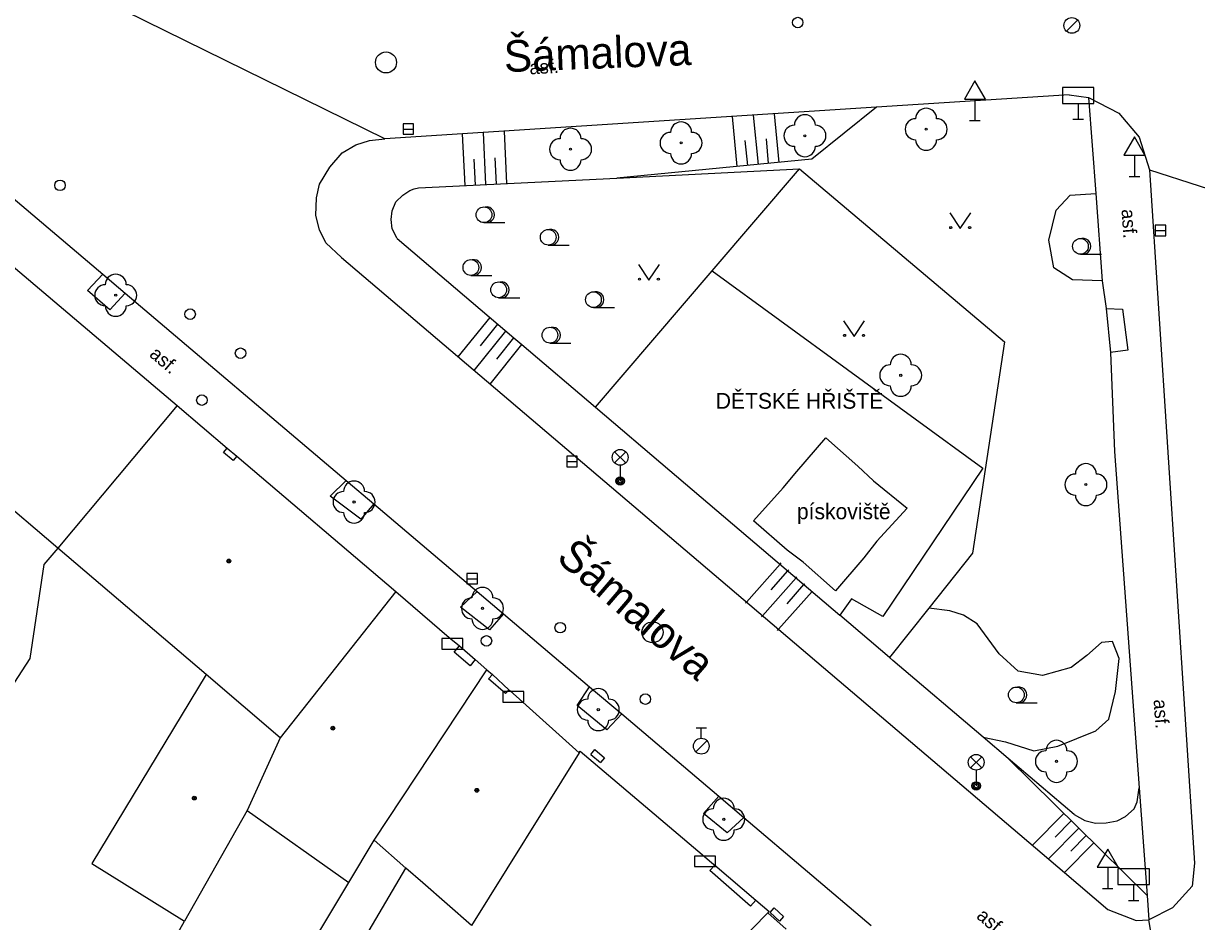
# Model space of a CAD drawing. Extents: x -596229 to -595156, y -1161237 to -1159376.
# Drawn here: x -596136.3 to -596080.4, y -1161085 to -1161042.3 of the extents above; entities that cross this region are included whole.
import ezdxf

# ---------------------------------------------------------------- set-up
doc = ezdxf.new("R2010")
doc.units = 0
for name, color, linetype in [('DOP - rozhrani ploch obecne', 7, 'Continuous'), ('Level 22', 7, 'Continuous'), ('Level 24', 7, 'Continuous'), ('Level 27', 7, 'Continuous'), ('Level 28', 7, 'Continuous'), ('Level 33', 7, 'Continuous'), ('Level 34', 7, 'Continuous'), ('Level 36', 7, 'Continuous'), ('Level 39', 7, 'Continuous'), ('Nazvy ulic', 7, 'Continuous'), ('silnoproud - povrch.  znaky a  RIS  skut. velikost', 7, 'Continuous'), ('slaboproud - povrch.  znaky a tel. budka skut. velikost', 7, 'Continuous'), ('Specificka linie pasportu komunikaci', 7, 'Continuous'), ('TM - budovy zdene_ betonove - NP', 7, 'Continuous'), ('TM - budovy zdene_ betonove - VP', 7, 'Continuous'), ('TM - chodniky - VP', 7, 'Continuous'), ('TM - horni hrana svahu', 7, 'Continuous'), ('TM - komunikace - VP', 7, 'Continuous'), ('TM - letecke snimky - pomocna linie', 7, 'Continuous'), ('TM - popis objektu', 7, 'Continuous'), ('TM - popis povrchu', 7, 'Continuous'), ('TM - poznamka', 7, 'Continuous'), ('TM - rozhrani kultur', 7, 'Continuous'), ('TM - rozhrani ploch obecne - VP', 7, 'Continuous'), ('TM - srafovani', 7, 'Continuous')]:
    doc.layers.add(name, color=color, linetype=linetype)

msp = doc.modelspace()

# ---------------------------------------------------------------- linework, layer by layer
at = {"layer": 'DOP - rozhrani ploch obecne'}
for points in [[(-596134.63, -1161067.25), (-596135.29, -1161068.02)], [(-596135.29, -1161068.02), (-596135.95, -1161072.49)], [(-596135.95, -1161072.49), (-596144.77, -1161086.08)], [(-596120.78, -1161083.15), (-596119.57, -1161081.14)], [(-596124.19, -1161088.83), (-596120.78, -1161083.15)], [(-596129.54, -1161086.67), (-596128.6, -1161085)]]:
    msp.add_lwpolyline(points, dxfattribs=at)
at = {"layer": 'Level 22'}
for centre in [(-596093.31, -1161047.31), (-596104.97, -1161047.96), (-596099.08, -1161047.62), (-596110.23, -1161048.26), (-596131.87, -1161055.21), (-596094.52, -1161059.02), (-596085.71, -1161064.22), (-596120.53, -1161065.05), (-596114.42, -1161070.11), (-596108.91, -1161074.93), (-596087.11, -1161077.39), (-596102.94, -1161080.15)]:
    msp.add_circle(centre, 0.05, dxfattribs=at)
for centre, start, end in [((-596093.31, -1161046.81), 0, 180), ((-596099.08, -1161047.12), 0, 180), ((-596093.81, -1161047.31), 90, 270), ((-596092.81, -1161047.31), 270, 90), ((-596110.23, -1161047.76), 0, 180), ((-596104.97, -1161047.46), 0, 180), ((-596099.58, -1161047.62), 90, 270), ((-596098.58, -1161047.62), 270, 90), ((-596110.73, -1161048.26), 90, 270), ((-596109.73, -1161048.26), 270, 90), ((-596105.47, -1161047.96), 90, 270), ((-596104.47, -1161047.96), 270, 90), ((-596093.31, -1161047.81), 180, 0), ((-596104.97, -1161048.46), 180, 0), ((-596099.08, -1161048.12), 180, 0), ((-596110.23, -1161048.76), 180, 0), ((-596131.87, -1161054.71), 0, 180), ((-596132.37, -1161055.21), 90, 270), ((-596131.37, -1161055.21), 270, 90), ((-596131.87, -1161055.71), 180, 0), ((-596094.52, -1161058.52), 0, 180), ((-596095.02, -1161059.02), 90, 270), ((-596094.02, -1161059.02), 270, 90), ((-596094.52, -1161059.52), 180, 0), ((-596085.71, -1161063.72), 0, 180), ((-596120.53, -1161064.55), 0, 180), ((-596086.21, -1161064.22), 90, 270), ((-596085.21, -1161064.22), 270, 90), ((-596121.03, -1161065.05), 90, 270), ((-596120.03, -1161065.05), 270, 90), ((-596085.71, -1161064.72), 180, 0), ((-596120.53, -1161065.55), 180, 0), ((-596114.42, -1161069.61), 0, 180), ((-596114.92, -1161070.11), 90, 270), ((-596113.92, -1161070.11), 270, 90), ((-596114.42, -1161070.61), 180, 0), ((-596108.91, -1161074.43), 0, 180), ((-596109.41, -1161074.93), 90, 270), ((-596108.41, -1161074.93), 270, 90), ((-596108.91, -1161075.43), 180, 0), ((-596087.11, -1161076.89), 0, 180), ((-596087.61, -1161077.39), 90, 270), ((-596086.61, -1161077.39), 270, 90), ((-596087.11, -1161077.89), 180, 0), ((-596102.94, -1161079.65), 0, 180), ((-596103.44, -1161080.15), 90, 270), ((-596102.44, -1161080.15), 270, 90), ((-596102.94, -1161080.65), 180, 0)]:
    msp.add_arc(centre, 0.5, start, end, dxfattribs=at)
at = {"layer": 'Level 24'}
for points in [[(-596116.347, -1161072.048), (-596115.347, -1161072.048), (-596115.347, -1161071.548), (-596116.347, -1161071.548)], [(-596113.447, -1161074.568), (-596112.447, -1161074.568), (-596112.447, -1161074.068), (-596113.447, -1161074.068)], [(-596104.337, -1161082.398), (-596103.337, -1161082.398), (-596103.337, -1161081.898), (-596104.337, -1161081.898)]]:
    msp.add_lwpolyline(points, close=True, dxfattribs=at)
at = {"layer": 'Level 27'}
for p, q in [((-596118.2, -1161047.3), (-596117.7, -1161047.3)), ((-596082.41, -1161052.13), (-596081.91, -1161052.13)), ((-596110.41, -1161063.12), (-596109.91, -1161063.12)), ((-596115.16, -1161068.7), (-596114.66, -1161068.7))]:
    msp.add_line(p, q, dxfattribs=at)
for points in [[(-596118.2, -1161047.55), (-596117.7, -1161047.55), (-596117.7, -1161047.05), (-596118.2, -1161047.05)], [(-596082.41, -1161052.38), (-596081.91, -1161052.38), (-596081.91, -1161051.88), (-596082.41, -1161051.88)], [(-596110.41, -1161063.37), (-596109.91, -1161063.37), (-596109.91, -1161062.87), (-596110.41, -1161062.87)], [(-596115.16, -1161068.95), (-596114.66, -1161068.95), (-596114.66, -1161068.45), (-596115.16, -1161068.45)]]:
    msp.add_lwpolyline(points, close=True, dxfattribs=at)
for centre in [(-596119.01, -1161044.13), (-596106.33, -1161071.25)]:
    msp.add_circle(centre, 0.5, dxfattribs=at)
at = {"layer": 'Level 28'}
for p, q in [((-596086.638, -1161042.642), (-596086.108, -1161042.112)), ((-596104.26, -1161075.795), (-596103.76, -1161075.795)), ((-596104.01, -1161076.295), (-596104.01, -1161075.795)), ((-596104.268, -1161076.942), (-596103.738, -1161076.412))]:
    msp.add_line(p, q, dxfattribs=at)
for centre, radius in [((-596099.42, -1161042.23), 0.25), ((-596086.38, -1161042.37), 0.375), ((-596134.52, -1161049.98), 0.25), ((-596128.33, -1161056.11), 0.25), ((-596125.93, -1161057.97), 0.25), ((-596127.77, -1161060.2), 0.25), ((-596110.72, -1161071.03), 0.25), ((-596114.23, -1161071.66), 0.25), ((-596106.67, -1161074.43), 0.25), ((-596104.01, -1161076.67), 0.375)]:
    msp.add_circle(centre, radius, dxfattribs=at)
at = {"layer": 'Level 33'}
for p, q in [((-596108.135, -1161063.19), (-596107.605, -1161062.66)), ((-596108.135, -1161062.66), (-596107.605, -1161063.19)), ((-596107.87, -1161063.3), (-596107.87, -1161064.05)), ((-596091.195, -1161077.7), (-596090.665, -1161077.17)), ((-596091.195, -1161077.17), (-596090.665, -1161077.7)), ((-596090.93, -1161077.81), (-596090.93, -1161078.56))]:
    msp.add_line(p, q, dxfattribs=at)
for centre, radius in [((-596107.87, -1161062.925), 0.375), ((-596107.87, -1161064.05), 0.2), ((-596107.87, -1161064.05), 0.145), ((-596107.87, -1161064.05), 0.0876), ((-596090.93, -1161077.435), 0.375), ((-596090.93, -1161078.56), 0.2), ((-596090.93, -1161078.56), 0.145), ((-596090.93, -1161078.56), 0.0876)]:
    msp.add_circle(centre, radius, dxfattribs=at)
at = {"layer": 'Level 34'}
for p, q in [((-596090.99, -1161045.872), (-596090.99, -1161046.89)), ((-596086.08, -1161046.08), (-596086.08, -1161046.83)), ((-596086.33, -1161046.83), (-596085.83, -1161046.83)), ((-596091.24, -1161046.89), (-596090.74, -1161046.89)), ((-596083.4, -1161048.542), (-596083.4, -1161049.56)), ((-596083.65, -1161049.56), (-596083.15, -1161049.56)), ((-596084.67, -1161082.432), (-596084.67, -1161083.45)), ((-596084.92, -1161083.45), (-596084.42, -1161083.45)), ((-596083.44, -1161083.26), (-596083.44, -1161084.01)), ((-596083.69, -1161084.01), (-596083.19, -1161084.01))]:
    msp.add_line(p, q, dxfattribs=at)
for points in [[(-596091.49, -1161045.872), (-596090.49, -1161045.872), (-596090.99, -1161045.006)], [(-596086.83, -1161046.08), (-596085.33, -1161046.08), (-596085.33, -1161045.33), (-596086.83, -1161045.33)], [(-596083.9, -1161048.542), (-596082.9, -1161048.542), (-596083.4, -1161047.676)], [(-596085.17, -1161082.432), (-596084.17, -1161082.432), (-596084.67, -1161081.566)], [(-596084.19, -1161083.26), (-596082.69, -1161083.26), (-596082.69, -1161082.51), (-596084.19, -1161082.51)]]:
    msp.add_lwpolyline(points, close=True, dxfattribs=at)
at = {"layer": 'Level 36'}
for p, q in [((-596114.35, -1161051.755), (-596113.35, -1161051.755)), ((-596111.29, -1161052.825), (-596110.29, -1161052.825)), ((-596085.97, -1161053.255), (-596084.97, -1161053.255)), ((-596114.97, -1161054.265), (-596113.97, -1161054.265)), ((-596113.65, -1161055.325), (-596112.65, -1161055.325)), ((-596109.14, -1161055.795), (-596108.14, -1161055.795)), ((-596111.21, -1161057.485), (-596110.21, -1161057.485)), ((-596089.02, -1161074.605), (-596088.02, -1161074.605))]:
    msp.add_line(p, q, dxfattribs=at)
for points in [[(-596092.19, -1161051.29), (-596091.69, -1161052.04), (-596091.19, -1161051.29)], [(-596107, -1161053.74), (-596106.5, -1161054.49), (-596106, -1161053.74)], [(-596097.24, -1161056.42), (-596096.74, -1161057.17), (-596096.24, -1161056.42)]]:
    msp.add_lwpolyline(points, dxfattribs=at)
for centre, radius in [((-596114.35, -1161051.38), 0.375), ((-596111.29, -1161052.45), 0.375), ((-596092.14, -1161051.99), 0.05), ((-596091.241, -1161051.99), 0.05), ((-596085.97, -1161052.88), 0.375), ((-596114.97, -1161053.89), 0.375), ((-596113.65, -1161054.95), 0.375), ((-596106.95, -1161054.44), 0.05), ((-596106.051, -1161054.44), 0.05), ((-596109.14, -1161055.42), 0.375), ((-596111.21, -1161057.11), 0.375), ((-596097.19, -1161057.12), 0.05), ((-596096.291, -1161057.12), 0.05), ((-596089.02, -1161074.23), 0.375)]:
    msp.add_circle(centre, radius, dxfattribs=at)
for centre in [(-596114.225, -1161051.38), (-596111.165, -1161052.45), (-596085.845, -1161052.88), (-596114.845, -1161053.89), (-596113.525, -1161054.95), (-596109.015, -1161055.42), (-596111.085, -1161057.11), (-596088.895, -1161074.23)]:
    msp.add_arc(centre, 0.375, 260.4059, 99.5941, dxfattribs=at)
at = {"layer": 'Level 39'}
for centre, radius in [((-596126.49, -1161067.86), 0.09), ((-596126.49, -1161067.86), 0.0398), ((-596121.54, -1161075.81), 0.09), ((-596121.54, -1161075.81), 0.0398), ((-596114.69, -1161078.77), 0.09), ((-596128.13, -1161079.14), 0.09), ((-596128.13, -1161079.14), 0.0398), ((-596114.69, -1161078.77), 0.0398)]:
    msp.add_circle(centre, radius, dxfattribs=at)
at = {"layer": 'silnoproud - povrch.  znaky a  RIS  skut. velikost'}
msp.add_lwpolyline([(-596126.11, -1161062.87), (-596126.29, -1161063.08), (-596126.74, -1161062.69), (-596126.56, -1161062.48)], dxfattribs=at)
at = {"layer": 'slaboproud - povrch.  znaky a tel. budka skut. velikost'}
for points in [[(-596109.27, -1161077.06), (-596109.07, -1161076.83), (-596108.62, -1161077.22), (-596108.81, -1161077.45)], [(-596109.27, -1161077.06), (-596108.81, -1161077.45)], [(-596100.73, -1161084.59), (-596100.54, -1161084.37), (-596100.09, -1161084.77), (-596100.29, -1161084.99)], [(-596100.73, -1161084.59), (-596100.29, -1161084.99)]]:
    msp.add_lwpolyline(points, dxfattribs=at)
at = {"layer": 'Specificka linie pasportu komunikaci'}
for points in [[(-596119.06, -1161047.77), (-596131.42, -1161041.69)], [(-596082.68, -1161049.24), (-596075.59, -1161051.53)], [(-596084.75, -1161055.84), (-596084.54, -1161057.94)], [(-596080.48, -1161098.3), (-596082.72, -1161084.93)]]:
    msp.add_lwpolyline(points, dxfattribs=at)
at = {"layer": 'TM - budovy zdene_ betonove - NP'}
for points in [[(-596114.76, -1161072.55), (-596115.01, -1161072.84), (-596115.76, -1161072.2), (-596115.51, -1161071.9)], [(-596113.16, -1161073.98), (-596113.33, -1161074.17), (-596114.13, -1161073.47), (-596113.95, -1161073.26)], [(-596101.42, -1161083.99), (-596101.66, -1161084.28), (-596103.61, -1161082.59), (-596103.37, -1161082.33)]]:
    msp.add_lwpolyline(points, dxfattribs=at)
at = {"layer": 'TM - budovy zdene_ betonove - VP'}
for points in [[(-596139.98, -1161051.12), (-596128.94, -1161060.45)], [(-596128.94, -1161060.45), (-596134.63, -1161067.25)], [(-596128.94, -1161060.45), (-596126.56, -1161062.48)], [(-596134.63, -1161067.25), (-596140.89, -1161061.91)], [(-596126.56, -1161062.48), (-596126.11, -1161062.87)], [(-596126.11, -1161062.87), (-596118.54, -1161069.31)], [(-596127.57, -1161073.26), (-596134.63, -1161067.25)], [(-596118.54, -1161069.31), (-596124.04, -1161076.27)], [(-596118.54, -1161069.31), (-596116, -1161071.49), (-596115.51, -1161071.9)], [(-596115.51, -1161071.9), (-596114.76, -1161072.55)], [(-596114.76, -1161072.55), (-596114.21, -1161073.03)], [(-596119.57, -1161081.14), (-596114.21, -1161073.03)], [(-596114.21, -1161073.03), (-596113.95, -1161073.26)], [(-596127.57, -1161073.26), (-596133.01, -1161082.25)], [(-596124.04, -1161076.27), (-596127.57, -1161073.26)], [(-596113.95, -1161073.26), (-596113.16, -1161073.98)], [(-596113.16, -1161073.98), (-596113.1, -1161074.03), (-596112.66, -1161074.43), (-596109.82, -1161076.99)], [(-596124.04, -1161076.27), (-596124.44, -1161077.14), (-596125.61, -1161079.73)], [(-596109.82, -1161076.99), (-596114.94, -1161085.2)], [(-596109.82, -1161076.99), (-596109.77, -1161076.9)], [(-596109.77, -1161076.9), (-596103.97, -1161081.82), (-596103.5, -1161082.22), (-596103.37, -1161082.33)], [(-596125.61, -1161079.73), (-596128.6, -1161085)], [(-596118.06, -1161082.47), (-596119.57, -1161081.14)], [(-596133.01, -1161082.25), (-596128.6, -1161085)], [(-596114.94, -1161085.2), (-596117.26, -1161083.17), (-596118.06, -1161082.47)], [(-596103.37, -1161082.33), (-596101.42, -1161083.99)], [(-596101.42, -1161083.99), (-596100.78, -1161084.53)], [(-596102.28, -1161086.07), (-596100.85, -1161084.6)], [(-596100.78, -1161084.53), (-596100.85, -1161084.6)], [(-596100.85, -1161084.6), (-596099.97, -1161085.38)]]:
    msp.add_lwpolyline(points, dxfattribs=at)
at = {"layer": 'TM - chodniky - VP'}
for points in [[(-596085.58, -1161045.8), (-596085.24, -1161050.37)], [(-596085.24, -1161050.37), (-596084.93, -1161054.53)], [(-596131.42, -1161055.11), (-596132.15, -1161055.91), (-596133.22, -1161054.99), (-596132.49, -1161054.2)], [(-596084.93, -1161054.53), (-596084.75, -1161055.84)], [(-596084.75, -1161055.84), (-596083.97, -1161055.87), (-596083.71, -1161057.82), (-596084.54, -1161057.94)], [(-596084.54, -1161057.94), (-596084.35, -1161062.65)], [(-596084.35, -1161062.65), (-596083.18, -1161078.65)], [(-596119.59, -1161065.14), (-596120.21, -1161065.86), (-596121.66, -1161064.77), (-596120.9, -1161064.03)], [(-596113.42, -1161070.37), (-596114.09, -1161071.13), (-596115.46, -1161070.05), (-596114.67, -1161069.31)], [(-596107.79, -1161075.13), (-596108.51, -1161075.89), (-596109.91, -1161074.73), (-596109.32, -1161073.84)], [(-596083.18, -1161078.65), (-596082.8, -1161083.78)], [(-596101.98, -1161080.06), (-596102.78, -1161080.8), (-596103.9, -1161079.87), (-596103.17, -1161079.05)], [(-596082.8, -1161083.78), (-596082.72, -1161084.93)]]:
    msp.add_lwpolyline(points, dxfattribs=at)
at = {"layer": 'TM - horni hrana svahu'}
for points in [[(-596095.67, -1161046.26), (-596098.75, -1161048.74)], [(-596098.75, -1161048.74), (-596108.02, -1161049.63)], [(-596089.41, -1161077.25), (-596082.8, -1161083.78)]]:
    msp.add_lwpolyline(points, dxfattribs=at)
at = {"layer": 'TM - komunikace - VP'}
for points in [[(-596086.5, -1161045.67), (-596095.67, -1161046.26)], [(-596086.5, -1161045.67), (-596085.58, -1161045.8)], [(-596095.67, -1161046.26), (-596119.06, -1161047.77)], [(-596085.58, -1161045.8), (-596084.14, -1161046.54)], [(-596084.14, -1161046.54), (-596083.18, -1161047.69)], [(-596121.13, -1161053.42), (-596121.87, -1161052.72), (-596122.18, -1161052.1), (-596122.35, -1161051.41), (-596122.31, -1161050.58), (-596122.18, -1161049.92), (-596121.69, -1161049.12), (-596121.1, -1161048.43), (-596120.45, -1161048.05), (-596119.79, -1161047.84), (-596119.06, -1161047.77)], [(-596083.18, -1161047.69), (-596082.68, -1161049.24)], [(-596082.68, -1161049.24), (-596080.54, -1161082.23)], [(-596137.07, -1161050.32), (-596132.49, -1161054.2)], [(-596121.13, -1161053.42), (-596086.73, -1161082.68), (-596084.67, -1161084.44), (-596083.31, -1161084.97), (-596082.72, -1161084.93)], [(-596132.49, -1161054.2), (-596131.42, -1161055.11)], [(-596131.42, -1161055.11), (-596120.9, -1161064.03)], [(-596120.9, -1161064.03), (-596119.59, -1161065.14)], [(-596119.59, -1161065.14), (-596114.67, -1161069.31)], [(-596114.67, -1161069.31), (-596113.42, -1161070.37)], [(-596113.42, -1161070.37), (-596109.32, -1161073.84)], [(-596109.32, -1161073.84), (-596107.79, -1161075.13)], [(-596107.79, -1161075.13), (-596103.17, -1161079.05)], [(-596103.17, -1161079.05), (-596101.98, -1161080.06)], [(-596101.98, -1161080.06), (-596095.92, -1161085.2)], [(-596080.54, -1161082.23), (-596080.65, -1161083.33)], [(-596080.65, -1161083.33), (-596081.59, -1161084.37)], [(-596081.59, -1161084.37), (-596082.72, -1161084.93)]]:
    msp.add_lwpolyline(points, dxfattribs=at)
at = {"layer": 'TM - letecke snimky - pomocna linie'}
for points in [[(-596103.49, -1161054.05), (-596099.33, -1161049.2)], [(-596099.33, -1161049.2), (-596089.58, -1161057.43), (-596091.11, -1161067.49), (-596093.19, -1161070.1)], [(-596109.05, -1161060.54), (-596103.49, -1161054.05)], [(-596105.51, -1161063.55), (-596097.41, -1161070.44)], [(-596093.19, -1161070.1), (-596095.05, -1161072.45)], [(-596125.61, -1161079.73), (-596120.78, -1161083.15)], [(-596122.4, -1161089.83), (-596118.06, -1161082.47)]]:
    msp.add_lwpolyline(points, dxfattribs=at)
at = {"layer": 'TM - rozhrani kultur'}
for points in [[(-596084.93, -1161054.53), (-596086.34, -1161054.47), (-596087.24, -1161053.91), (-596087.48, -1161052.59), (-596087.13, -1161051.16), (-596086.46, -1161050.44), (-596085.24, -1161050.37)], [(-596090.6, -1161076.24), (-596089.53, -1161076.46), (-596088.19, -1161076.89), (-596087.05, -1161076.67), (-596085.23, -1161075.94), (-596084.62, -1161075.39), (-596084.3, -1161074.07), (-596084.13, -1161072.5), (-596084.44, -1161071.69), (-596084.97, -1161071.73), (-596085.66, -1161072.35), (-596086.41, -1161072.92), (-596087.77, -1161073.3), (-596088.93, -1161073.1), (-596089.84, -1161072.28), (-596090.88, -1161070.84), (-596091.54, -1161070.43), (-596092.19, -1161070.23), (-596093.19, -1161070.1)]]:
    msp.add_lwpolyline(points, dxfattribs=at)
at = {"layer": 'TM - rozhrani ploch obecne - VP'}
for points in [[(-596117.46, -1161050.1), (-596108.02, -1161049.63)], [(-596108.02, -1161049.63), (-596099.33, -1161049.2)], [(-596118.48, -1161052.51), (-596118.71, -1161052.05), (-596118.76, -1161051.6), (-596118.71, -1161051.19), (-596118.54, -1161050.77), (-596118.21, -1161050.44), (-596117.88, -1161050.22), (-596117.67, -1161050.15), (-596117.46, -1161050.1)], [(-596118.48, -1161052.51), (-596112.93, -1161057.24), (-596112.55, -1161057.56), (-596109.05, -1161060.54)], [(-596103.49, -1161054.05), (-596090.62, -1161063.44), (-596095.37, -1161070.5), (-596096.86, -1161069.65), (-596097.41, -1161070.44)], [(-596109.05, -1161060.54), (-596105.51, -1161063.55)], [(-596099.46, -1161063.59), (-596098.09, -1161061.99), (-596096.56, -1161063.35)], [(-596100.12, -1161064.37), (-596099.46, -1161063.59)], [(-596096.56, -1161063.35), (-596095.82, -1161064.04)], [(-596095.82, -1161064.04), (-596094.21, -1161065.35), (-596095.65, -1161066.91)], [(-596099.92, -1161067.34), (-596101.53, -1161065.94), (-596100.12, -1161064.37)], [(-596095.65, -1161066.91), (-596096.28, -1161067.71)], [(-596099.16, -1161067.91), (-596099.92, -1161067.34)], [(-596096.28, -1161067.71), (-596097.63, -1161069.28), (-596099.16, -1161067.91)], [(-596095.05, -1161072.45), (-596097.41, -1161070.44)], [(-596090.6, -1161076.24), (-596094.89, -1161072.59), (-596095.05, -1161072.45)], [(-596089.41, -1161077.25), (-596090.6, -1161076.24)], [(-596086.27, -1161079.92), (-596089.41, -1161077.25)], [(-596086.27, -1161079.92), (-596085.76, -1161080.2), (-596085.25, -1161080.34), (-596084.75, -1161080.32), (-596084.22, -1161080.22), (-596083.82, -1161080.01), (-596083.42, -1161079.65), (-596083.27, -1161079.32), (-596083.18, -1161078.65)]]:
    msp.add_lwpolyline(points, dxfattribs=at)
at = {"layer": 'TM - srafovani'}
for points in [[(-596102.54, -1161046.7), (-596102.31, -1161049.08)], [(-596101.54, -1161046.64), (-596101.31, -1161048.99)], [(-596100.54, -1161046.57), (-596100.32, -1161048.89)], [(-596113.39, -1161047.4), (-596113.27, -1161049.89)], [(-596115.39, -1161047.53), (-596115.26, -1161049.99)], [(-596114.39, -1161047.47), (-596114.27, -1161049.94)], [(-596101.93, -1161047.84), (-596101.81, -1161049.03)], [(-596100.93, -1161047.77), (-596100.82, -1161048.94)], [(-596114.83, -1161048.73), (-596114.77, -1161049.97)], [(-596113.83, -1161048.67), (-596113.77, -1161049.92)], [(-596115.58, -1161058.14), (-596114.06, -1161056.27)], [(-596114.82, -1161058.79), (-596113.31, -1161056.92)], [(-596114.51, -1161057.61), (-596113.69, -1161056.59)], [(-596113.74, -1161058.25), (-596112.93, -1161057.24)], [(-596114.06, -1161059.44), (-596112.55, -1161057.56)], [(-596101.91, -1161069.86), (-596101.86, -1161069.81), (-596100.26, -1161068.01), (-596100.21, -1161067.95)], [(-596101.15, -1161070.51), (-596101.1, -1161070.46), (-596099.5, -1161068.66), (-596099.46, -1161068.61)], [(-596100.68, -1161069.23), (-596099.89, -1161068.33), (-596099.84, -1161068.28)], [(-596099.93, -1161069.89), (-596099.13, -1161068.98), (-596099.09, -1161068.94)], [(-596100.39, -1161071.16), (-596100.34, -1161071.1), (-596098.74, -1161069.31)], [(-596088.25, -1161081.38), (-596086.76, -1161079.87)], [(-596087.17, -1161081), (-596086.41, -1161080.22)], [(-596087.49, -1161082.03), (-596086.05, -1161080.57)], [(-596086.43, -1161081.67), (-596085.69, -1161080.92)], [(-596086.73, -1161082.68), (-596085.34, -1161081.28)]]:
    msp.add_lwpolyline(points, dxfattribs=at)

# ---------------------------------------------------------------- texts
at = {"layer": 'Nazvy ulic'}
for rotation, p in [(2.2011, (-596113.374, -1161044.592)), (319.3455, (-596110.963, -1161067.795))]:
    msp.add_text('Šámalova', height=1.5, rotation=rotation, dxfattribs=at).set_placement(p)
at = {"layer": 'TM - popis objektu'}
msp.add_text('DĚTSKÉ HŘIŠTĚ', height=0.75, dxfattribs=at).set_placement((-596103.32, -1161060.61))
at = {"layer": 'TM - popis povrchu'}
for rotation, p in [(3.15, (-596112.17, -1161044.7)), (274.25, (-596084.02, -1161051.13)), (319.8, (-596130.31, -1161058.09)), (274.18, (-596082.49, -1161074.46)), (319.71, (-596090.96, -1161084.82))]:
    msp.add_text('asf.', height=0.65, rotation=rotation, dxfattribs=at).set_placement(p)
at = {"layer": 'TM - poznamka'}
msp.add_text('pískoviště', height=0.75, dxfattribs=at).set_placement((-596099.46, -1161065.87))

doc.saveas('drawing.dxf')
